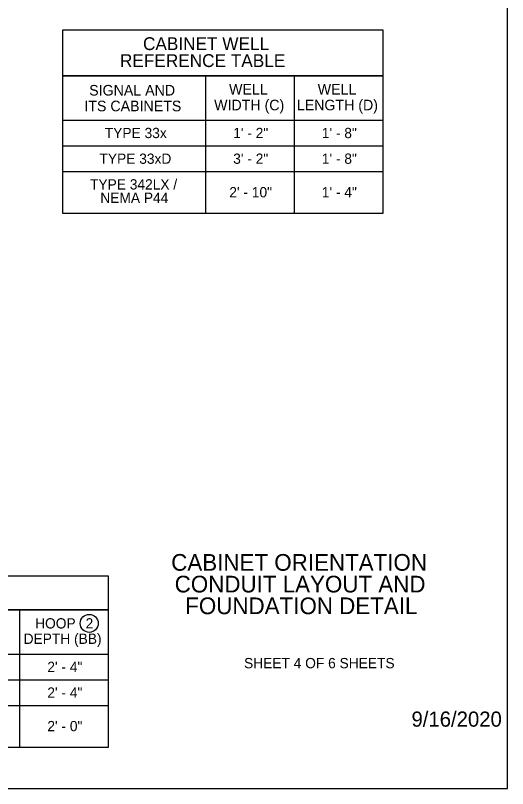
# Model space of a CAD drawing. Extents: x 99862 to 103151, y 100000 to 117076.
# Drawn here: x 102386 to 103151, y 109000 to 110203 of the extents above; entities that cross this region are included whole.
import ezdxf

# ---------------------------------------------------------------- set-up
doc = ezdxf.new("R2010")
doc.units = 0
for name, color, linetype in [('Level 1', 7, 'Continuous'), ('Level 15', 7, 'Continuous'), ('Level 20', 7, 'Continuous'), ('Level 40', 7, 'Continuous'), ('Level 62', 7, 'Continuous')]:
    doc.layers.add(name, color=color, linetype=linetype)

msp = doc.modelspace()

# ---------------------------------------------------------------- linework, layer by layer
at = {"layer": 'Level 1'}
msp.add_lwpolyline([(99862, 108999.5), (103151, 108999.5), (103151, 111075.5), (99862, 111075.5)], close=True, dxfattribs=at)
at = {"layer": 'Level 20'}
msp.add_circle((102500.2, 109256.7), 14, dxfattribs=at)
at = {"layer": 'Level 40'}
for p, q in [((102681.1, 110109.3), (102681.1, 109894.8)), ((102819, 110109.3), (102819, 109894.8)), ((102459.4, 110040.2), (102956.9, 110040.2)), ((102459.4, 110000.2), (102956.9, 110000.2)), ((102459.4, 109960.2), (102956.9, 109960.2)), ((102392, 109278), (102392, 109063.5)), ((101480.9, 109208.9), (102529.9, 109208.9)), ((101480.9, 109168.9), (102529.9, 109168.9)), ((101480.9, 109128.9), (102529.9, 109128.9))]:
    msp.add_line(p, q, dxfattribs=at)
for points in [[(102459.4, 110180.8), (102956.9, 110180.8), (102956.9, 110109.3), (102459.4, 110109.3)], [(102459.4, 110109.3), (102956.9, 110109.3), (102956.9, 109894.8), (102459.4, 109894.8)], [(101480.9, 109330.7), (102529.9, 109330.7), (102529.9, 109278), (101480.9, 109278)], [(101480.9, 109278), (102529.9, 109278), (102529.9, 109063.5), (101480.9, 109063.5)]]:
    msp.add_lwpolyline(points, close=True, dxfattribs=at)

# ---------------------------------------------------------------- texts
at = {"layer": 'Level 15'}
msp.add_text('9/16/2020', height=23.62, dxfattribs=at).set_placement((103001.6, 109095.8))
at = {"layer": 'Level 20'}
for s, height, p in [('CABINET WELL', 20, (102583.9, 110149.3)), ('REFERENCE TABLE', 20, (102548.1, 110122.9)), ('SIGNAL AND', 16.5, (102500.2, 110078.5)), ('WELL', 16.5, (102717.8, 110080)), ('WELL', 16.5, (102855.7, 110080)), ('ITS CABINETS', 16.5, (102492.7, 110054)), ('WIDTH (C)', 16.5, (102694.6, 110055.5)), ('LENGTH (D)', 16.5, (102823.2, 110055.5)), ('TYPE 33x', 16, (102524.5, 110012.2)), ('1\' - 2"', 16, (102724.2, 110012.2)), ('1\' - 8"', 16, (102862.1, 110012.2)), ('TYPE 33xD', 16, (102516.2, 109972.2)), ('3\' - 2"', 16, (102724.2, 109972.2)), ('1\' - 8"', 16, (102862.1, 109972.2)), ('TYPE 342LX /', 16, (102501.5, 109932.2)), ('2\' - 10"', 16, (102718.2, 109920)), ('1\' - 4"', 16, (102862.1, 109920)), ('NEMA P44', 16, (102517.5, 109911.3)), ('HOOP ', 16, (102416.1, 109248.7)), ('2', 16, (102494.6, 109248.7)), ('DEPTH (BB)', 16, (102398.2, 109224.7)), ('2\' - 4"', 16, (102435.1, 109180.9)), ('2\' - 4"', 16, (102435.1, 109140.9)), ('2\' - 0"', 16, (102435.1, 109088.7))]:
    msp.add_text(s, height=height, dxfattribs=at).set_placement(p)
at = {"layer": 'Level 62'}
for s, height, p in [('CABINET ORIENTATION', 26, (102627.8, 109338.6)), ('CONDUIT LAYOUT AND', 26, (102633.2, 109304.8)), ('FOUNDATION DETAIL', 26, (102649.6, 109271)), ('SHEET 4 OF 6 SHEETS', 16, (102741.1, 109186.8))]:
    msp.add_text(s, height=height, dxfattribs=at).set_placement(p)

doc.saveas('drawing.dxf')
